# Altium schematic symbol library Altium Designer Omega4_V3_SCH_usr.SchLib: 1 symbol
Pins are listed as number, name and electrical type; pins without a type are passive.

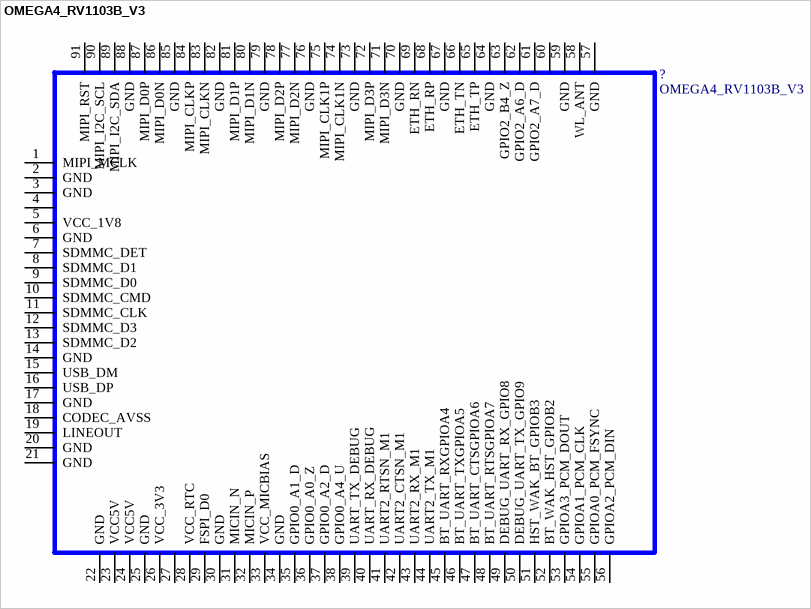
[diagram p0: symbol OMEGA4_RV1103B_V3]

## OMEGA4_RV1103B_V3
designator ?
footprint MODUL_RV1103B
pins: 1 MIPI_MCLK, 2 GND, 3 GND, 4, 5 VCC_1V8, 6 GND, 7 SDMMC_DET, 8 SDMMC_D1, 9 SDMMC_D0, 10 SDMMC_CMD, 11 SDMMC_CLK, 12 SDMMC_D3, 13 SDMMC_D2, 14 GND, 15 USB_DM, 16 USB_DP, 17 GND, 18 CODEC_AVSS, 19 LINEOUT, 20 GND, 21 GND, 22 GND, 23 VCC5V, 24 VCC5V, 25 GND, 26 VCC_3V3, 27, 28 VCC_RTC, 29 FSPI_D0, 30 GND, 31 MICIN_N, 32 MICIN_P, 33 VCC_MICBIAS, 34 GND, 35 GPIO0_A1_D, 36 GPIO0_A0_Z, 37 GPIO0_A2_D, 38 GPIO0_A4_U, 39 UART_TX_DEBUG, 40 UART_RX_DEBUG, 41 UART2_RTSN_M1, 42 UART2_CTSN_M1, 43 UART2_RX_M1, 44 UART2_TX_M1, 45 BT_UART_RXGPIOA4, 46 BT_UART_TXGPIOA5, 47 BT_UART_CTSGPIOA6, 48 BT_UART_RTSGPIOA7, 49 DEBUG_UART_RX_GPIO8, 50 DEBUG_UART_TX_GPIO9, 51 HST_WAK_BT_GPIOB3, 52 BT_WAK_HST_GPIOB2, 53 GPIOA3_PCM_DOUT, 54 GPIOA1_PCM_CLK, 55 GPIOA0_PCM_FSYNC, 56 GPIOA2_PCM_DIN, 57 GND, 58 WL_ANT, 59 GND, 60, 61 GPIO2_A7_D, 62 GPIO2_A6_D, 63 GPIO2_B4_Z, 64 GND, 65 ETH_TP, 66 ETH_TN, 67 GND, 68 ETH_RP, 69 ETH_RN, 70 GND, 71 MIPI_D3N, 72 MIPI_D3P, 73 GND, 74 MIPI_CLK1N, 75 MIPI_CLK1P, 76 GND, 77 MIPI_D2N, 78 MIPI_D2P, 79 GND, 80 MIPI_D1N, 81 MIPI_D1P, 82 GND, 83 MIPI_CLKN, 84 MIPI_CLKP, 85 GND, 86 MIPI_D0N, 87 MIPI_D0P, 88 GND, 89 MIPI_I2C_SDA, 90 MIPI_I2C_SCL, 91 MIPI_RST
